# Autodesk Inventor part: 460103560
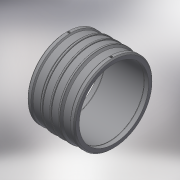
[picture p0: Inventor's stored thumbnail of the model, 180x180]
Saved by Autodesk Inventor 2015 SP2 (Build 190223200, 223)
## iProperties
Created: 2017-06
Part Number: 460103560
Material: Generic
Description: PLASSON LIGHTFIT COUPLER 560
Document SubType Name: Modeling
Designer: KIM
Mass: 23786.4 g
Surface Area: 16041.2 cm^2
Volume: 23786.4 cm^3
Density: 1 g/cm^3
Appearance: Default
Author: KIM
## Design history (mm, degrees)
derived "460103.ipt"
feature "Solid1::460103.ipt"
tag "TaggingFeature1"
body "Solid1"
other parameters: "d13" = 376, "d14" = 17.6296, "d15" = 188, "d16" = 188, "d19" = 3.52592, "d20" = 168 deg, "d22" = 634, "d23" = 645, "d24" = 614.98, "d25" = 135 deg, "d26" = 150.4, "d27" = 135 deg, "d29" = 317, "d35" = 15, "d39" = 0, "d40" = 4, "d41" = 14, "d42" = 0, "d43" = 135 deg, "d44" = 41.36, "d45" = 15.04, "d46" = 15.04, "d47" = 15.04, "d48" = 632.1, "d49" = 645, "d50" = 3.225, "d51" = 6, "d52" = 0, "L_" = 376, "L_1" = 188, "D_" = 645, "A_" = 317, "d_2" = 12
